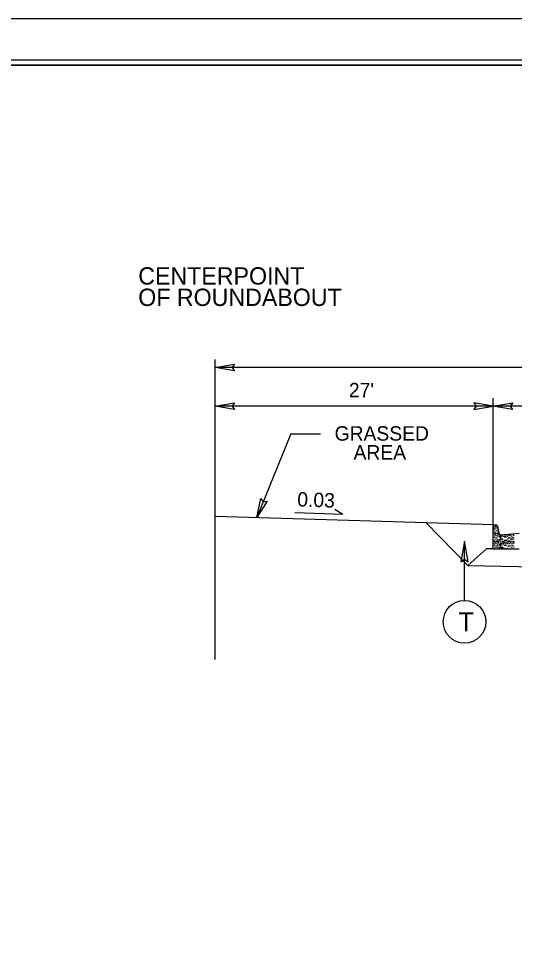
# Model space of a CAD drawing. Extents: x 1640342 to 1730599, y 538663 to 843747.
# Drawn here: x 1729959.6 to 1730007.7, y 538790.9 to 538882.2 of the extents above; entities that cross this region are included whole.
import ezdxf

# ---------------------------------------------------------------- set-up
doc = ezdxf.new("R2010")
doc.units = 0
for name, color, linetype in [('Default', 7, 'Continuous'), ('Prop Terminator CELL', 7, 'Continuous'), ('Sheet Plan CELL', 7, 'Continuous'), ('Sheet Plot Border Inside CELL', 7, 'Continuous'), ('Sheet Plot Border Outside CELL', 7, 'Continuous'), ('Typical Curb CELL', 7, 'Continuous'), ('Typical ID Circle CELL', 7, 'Continuous'), ('Typical Pavement Slope CELL', 7, 'Continuous'), ('Typical Pavement Slope Information CELL', 7, 'Continuous'), ('Typical Slope Point Local CELL', 7, 'Continuous'), ('Typical Terminator CELL', 7, 'Continuous'), ('Typical Text ID Circle CELL', 7, 'Continuous')]:
    doc.layers.add(name, color=color, linetype=linetype)

msp = doc.modelspace()

# ---------------------------------------------------------------- linework, layer by layer
at = {"layer": 'Default'}
for p, q in [((1729978.649, 538820.095), (1729978.649, 538849.183)), ((1730043.643, 538848.404), (1729978.649, 538848.404)), ((1730005.643, 538833.124), (1730005.643, 538845.435)), ((1730005.643, 538844.656), (1729978.649, 538844.656)), ((1730025.643, 538844.656), (1730005.643, 538844.656)), ((1729986.009, 538841.96), (1729982.691, 538833.852)), ((1729986.009, 538841.96), (1729988.889, 538841.96))]:
    msp.add_line(p, q, dxfattribs=at)
for points in [[(1729980.523, 538848.081), (1729978.649, 538848.404), (1729980.533, 538848.737), (1729980.294, 538848.404)], [(1729980.523, 538844.333), (1729978.649, 538844.656), (1729980.533, 538844.989), (1729980.294, 538844.656)], [(1730003.769, 538844.333), (1730005.643, 538844.656), (1730003.758, 538844.989), (1730003.998, 538844.656)], [(1730007.517, 538844.333), (1730005.643, 538844.656), (1730007.527, 538844.989), (1730007.288, 538844.656)]]:
    msp.add_lwpolyline(points, close=True, dxfattribs=at)
at = {"layer": 'Prop Terminator CELL'}
msp.add_lwpolyline([(1729983.694, 538835.455), (1729982.691, 538833.852), (1729983.094, 538835.712), (1729983.31, 538835.366)], close=True, dxfattribs=at)
at = {"layer": 'Sheet Plan CELL'}
for points in [[(1729873.99, 538667.718), (1729873.985, 538877.713), (1730133.983, 538877.721), (1730133.985, 538847.708), (1730173.993, 538847.706), (1730173.993, 538667.718)], [(1730173.998, 538877.718), (1729873.99, 538877.718), (1729873.99, 538667.718), (1730173.993, 538667.718)]]:
    msp.add_lwpolyline(points, close=True, dxfattribs=at)
at = {"layer": 'Sheet Plot Border Inside CELL'}
msp.add_lwpolyline([(1729843.293, 538667.216), (1730176.49, 538667.218), (1730176.493, 538878.216), (1729843.293, 538878.216)], close=True, dxfattribs=at)
at = {"layer": 'Sheet Plot Border Outside CELL'}
msp.add_lwpolyline([(1729840.693, 538663.216), (1730177.393, 538663.216), (1730177.393, 538882.216), (1729840.693, 538882.216)], close=True, dxfattribs=at)
at = {"layer": 'Typical Curb CELL'}
for p, q in [((1730005.848, 538833.039), (1730005.81, 538832.998)), ((1730005.81, 538832.998), (1730005.835, 538832.931)), ((1730005.835, 538832.931), (1730005.848, 538833.039)), ((1730005.711, 538832.721), (1730005.674, 538832.68)), ((1730005.674, 538832.68), (1730005.687, 538832.643)), ((1730005.711, 538832.402), (1730005.674, 538832.361)), ((1730005.674, 538832.361), (1730005.687, 538832.324)), ((1730005.701, 538832.644), (1730005.711, 538832.721)), ((1730005.701, 538832.324), (1730005.711, 538832.402)), ((1730005.848, 538832.271), (1730005.81, 538832.23)), ((1730005.81, 538832.23), (1730005.835, 538832.163)), ((1730005.835, 538832.163), (1730005.848, 538832.271)), ((1730006.083, 538832.308), (1730006.117, 538832.356)), ((1730006.1, 538832.233), (1730006.083, 538832.308)), ((1730006.117, 538832.356), (1730006.1, 538832.233)), ((1730006.224, 538832.095), (1730006.254, 538832.083)), ((1730006.239, 538831.993), (1730006.224, 538832.095)), ((1730006.254, 538832.083), (1730006.239, 538831.993)), ((1730006.371, 538832.13), (1730006.333, 538832.089)), ((1730006.333, 538832.089), (1730006.357, 538832.022)), ((1730006.357, 538832.022), (1730006.371, 538832.13)), ((1730006.621, 538832.117), (1730006.604, 538832.191)), ((1730006.745, 538831.978), (1730006.775, 538831.967)), ((1730006.753, 538831.919), (1730006.745, 538831.978)), ((1730006.891, 538832.013), (1730006.854, 538831.972)), ((1730006.881, 538831.925), (1730006.891, 538832.013)), ((1730006.967, 538832.211), (1730006.992, 538832.144)), ((1730007.356, 538832.247), (1730007.318, 538832.206)), ((1730007.318, 538832.206), (1730007.343, 538832.139)), ((1730007.343, 538832.139), (1730007.356, 538832.247)), ((1730007.608, 538832.209), (1730007.591, 538832.284)), ((1730005.711, 538831.953), (1730005.674, 538831.912)), ((1730005.674, 538831.912), (1730005.687, 538831.875)), ((1730005.711, 538831.634), (1730005.674, 538831.593)), ((1730005.674, 538831.593), (1730005.687, 538831.556)), ((1730005.711, 538831.147), (1730005.674, 538831.106)), ((1730005.674, 538831.106), (1730005.687, 538831.069)), ((1730005.701, 538831.875), (1730005.711, 538831.953)), ((1730005.701, 538831.556), (1730005.711, 538831.634)), ((1730005.701, 538831.069), (1730005.711, 538831.147)), ((1730005.848, 538831.465), (1730005.81, 538831.424)), ((1730005.81, 538831.424), (1730005.835, 538831.357)), ((1730005.835, 538831.357), (1730005.848, 538831.465)), ((1730006.083, 538831.502), (1730006.117, 538831.55)), ((1730006.1, 538831.427), (1730006.083, 538831.502)), ((1730006.117, 538831.55), (1730006.1, 538831.427)), ((1730006.224, 538831.775), (1730006.254, 538831.764)), ((1730006.239, 538831.674), (1730006.224, 538831.775)), ((1730006.224, 538831.288), (1730006.254, 538831.277)), ((1730006.239, 538831.187), (1730006.224, 538831.288)), ((1730006.254, 538831.764), (1730006.239, 538831.674)), ((1730006.254, 538831.277), (1730006.239, 538831.187)), ((1730006.324, 538831.901), (1730006.326, 538831.901)), ((1730006.324, 538831.582), (1730006.326, 538831.582)), ((1730006.324, 538831.095), (1730006.326, 538831.095)), ((1730006.371, 538831.811), (1730006.333, 538831.77)), ((1730006.333, 538831.77), (1730006.357, 538831.702)), ((1730006.371, 538831.324), (1730006.333, 538831.283)), ((1730006.333, 538831.283), (1730006.357, 538831.215)), ((1730006.357, 538831.702), (1730006.371, 538831.811)), ((1730006.357, 538831.215), (1730006.371, 538831.324)), ((1730006.367, 538831.903), (1730006.371, 538831.903)), ((1730006.367, 538831.584), (1730006.371, 538831.584)), ((1730006.367, 538831.097), (1730006.371, 538831.097)), ((1730006.55, 538831.911), (1730006.554, 538831.911)), ((1730006.55, 538831.591), (1730006.554, 538831.592)), ((1730006.55, 538831.105), (1730006.554, 538831.105)), ((1730006.604, 538831.385), (1730006.638, 538831.433)), ((1730006.621, 538831.31), (1730006.604, 538831.385)), ((1730006.638, 538831.433), (1730006.621, 538831.31)), ((1730006.745, 538831.659), (1730006.775, 538831.647)), ((1730006.753, 538831.6), (1730006.745, 538831.659)), ((1730006.745, 538831.172), (1730006.775, 538831.16)), ((1730006.753, 538831.113), (1730006.745, 538831.172)), ((1730006.775, 538831.967), (1730006.767, 538831.92)), ((1730006.775, 538831.647), (1730006.767, 538831.601)), ((1730006.775, 538831.16), (1730006.767, 538831.114)), ((1730006.854, 538831.972), (1730006.871, 538831.924)), ((1730006.891, 538831.694), (1730006.854, 538831.653)), ((1730006.854, 538831.653), (1730006.871, 538831.605)), ((1730006.891, 538831.207), (1730006.854, 538831.166)), ((1730006.854, 538831.166), (1730006.871, 538831.118)), ((1730006.881, 538831.605), (1730006.891, 538831.694)), ((1730006.881, 538831.118), (1730006.891, 538831.207)), ((1730006.967, 538831.405), (1730006.992, 538831.338)), ((1730007.219, 538831.93), (1730007.182, 538831.889)), ((1730007.182, 538831.889), (1730007.195, 538831.851)), ((1730007.219, 538831.61), (1730007.182, 538831.569)), ((1730007.182, 538831.569), (1730007.195, 538831.532)), ((1730007.219, 538831.147), (1730007.182, 538831.106)), ((1730007.182, 538831.106), (1730007.195, 538831.069)), ((1730007.209, 538831.852), (1730007.219, 538831.93)), ((1730007.209, 538831.533), (1730007.219, 538831.61)), ((1730007.209, 538831.069), (1730007.219, 538831.147)), ((1730007.356, 538831.465), (1730007.318, 538831.424)), ((1730007.318, 538831.424), (1730007.343, 538831.357)), ((1730007.343, 538831.357), (1730007.356, 538831.465)), ((1730007.591, 538831.502), (1730007.625, 538831.55)), ((1730007.608, 538831.427), (1730007.591, 538831.502)), ((1730007.625, 538831.55), (1730007.608, 538831.427)), ((1730003.16, 538829.222), (1730004.992, 538830.83)), ((1730005.649, 538830.83), (1730004.992, 538830.83)), ((1730006.224, 538830.969), (1730006.254, 538830.958)), ((1730006.239, 538830.868), (1730006.224, 538830.969)), ((1730006.254, 538830.958), (1730006.239, 538830.868)), ((1730006.371, 538831.004), (1730006.333, 538830.963)), ((1730006.333, 538830.963), (1730006.357, 538830.896)), ((1730006.357, 538830.896), (1730006.371, 538831.004)), ((1730006.745, 538830.853), (1730006.775, 538830.841)), ((1730006.753, 538830.794), (1730006.745, 538830.853)), ((1730006.775, 538830.841), (1730006.767, 538830.794)), ((1730006.891, 538830.888), (1730006.854, 538830.847))]:
    msp.add_line(p, q, dxfattribs=at)
for centre in [(1730005.643, 538833.035), (1730005.653, 538833.118), (1730005.677, 538832.957), (1730005.703, 538833.095), (1730005.728, 538832.935), (1730005.905, 538833.053), (1730005.908, 538832.883), (1730005.911, 538833.078), (1730005.958, 538833.014), (1730005.964, 538832.902), (1730005.967, 538833.096), (1730006.083, 538832.941), (1730005.643, 538832.267), (1730005.653, 538832.349), (1730005.668, 538832.875), (1730005.668, 538832.556), (1730005.668, 538832.107), (1730005.677, 538832.189), (1730005.703, 538832.327), (1730005.728, 538832.167), (1730005.745, 538832.781), (1730005.745, 538832.462), (1730005.745, 538832.013), (1730005.758, 538832.669), (1730005.758, 538832.35), (1730005.828, 538832.664), (1730005.828, 538832.344), (1730005.837, 538832.746), (1730005.837, 538832.427), (1730005.837, 538831.978), (1730005.853, 538832.855), (1730005.853, 538832.536), (1730005.853, 538832.087), (1730005.901, 538832.859), (1730005.901, 538832.54), (1730005.901, 538832.091), (1730005.905, 538832.285), (1730005.908, 538832.564), (1730005.908, 538832.115), (1730005.911, 538832.309), (1730005.947, 538832.668), (1730005.947, 538832.349), (1730005.955, 538832.82), (1730005.955, 538832.5), (1730005.955, 538832.052), (1730005.958, 538832.246), (1730005.964, 538832.583), (1730005.964, 538832.134), (1730005.967, 538832.328), (1730006.003, 538832.687), (1730006.003, 538832.367), (1730006.015, 538832.88), (1730006.015, 538832.56), (1730006.015, 538832.112), (1730006.054, 538832.664), (1730006.054, 538832.345), (1730006.063, 538832.731), (1730006.063, 538832.412), (1730006.072, 538832.813), (1730006.072, 538832.494), (1730006.072, 538832.045), (1730006.083, 538832.173), (1730006.139, 538832.569), (1730006.139, 538832.12), (1730006.145, 538832.199), (1730006.151, 538832.427), (1730006.151, 538831.978), (1730006.164, 538832.308), (1730006.201, 538832.188), (1730006.211, 538832.012), (1730006.226, 538832.319), (1730006.284, 538832.154), (1730006.29, 538832.089), (1730006.322, 538831.973), (1730006.417, 538832.077), (1730006.423, 538831.976), (1730006.467, 538832.151), (1730006.489, 538832.033), (1730006.496, 538832.058), (1730006.518, 538832.129), (1730006.542, 538831.994), (1730006.552, 538832.076), (1730006.604, 538832.056), (1730006.66, 538832.004), (1730006.666, 538832.083), (1730006.685, 538832.191), (1730006.722, 538832.071), (1730006.746, 538832.202), (1730006.795, 538832.206), (1730006.804, 538832.038), (1730006.811, 538831.972), (1730006.848, 538832.167), (1730006.925, 538832.073), (1730006.993, 538831.999), (1730007.012, 538832.107), (1730007.05, 538831.988), (1730007.074, 538832.119), (1730007.123, 538832.122), (1730007.129, 538832.147), (1730007.151, 538832.243), (1730007.176, 538832.083), (1730007.185, 538832.165), (1730007.236, 538832.143), (1730007.253, 538831.989), (1730007.361, 538832.064), (1730007.409, 538832.067), (1730007.413, 538832.262), (1730007.416, 538832.092), (1730007.463, 538832.028), (1730007.466, 538832.222), (1730007.472, 538832.11), (1730007.523, 538832.088), (1730007.58, 538832.021), (1730007.591, 538832.149), (1730007.647, 538832.097), (1730007.653, 538832.175), (1730007.672, 538832.284), (1730005.643, 538831.461), (1730005.653, 538831.543), (1730005.668, 538831.787), (1730005.668, 538831.3), (1730005.677, 538831.383), (1730005.703, 538831.521), (1730005.728, 538831.36), (1730005.745, 538831.694), (1730005.745, 538831.207), (1730005.758, 538831.901), (1730005.758, 538831.582), (1730005.758, 538831.095), (1730005.828, 538831.896), (1730005.828, 538831.576), (1730005.828, 538831.089), (1730005.837, 538831.659), (1730005.837, 538831.172), (1730005.853, 538831.768), (1730005.853, 538831.281), (1730005.901, 538831.772), (1730005.901, 538831.285), (1730005.905, 538831.479), (1730005.908, 538831.796), (1730005.908, 538831.309), (1730005.911, 538831.503), (1730005.947, 538831.9), (1730005.947, 538831.58), (1730005.947, 538831.093), (1730005.955, 538831.732), (1730005.955, 538831.245), (1730005.958, 538831.44), (1730005.964, 538831.815), (1730005.964, 538831.328), (1730005.967, 538831.522), (1730006.003, 538831.918), (1730006.003, 538831.599), (1730006.003, 538831.112), (1730006.015, 538831.792), (1730006.015, 538831.305), (1730006.054, 538831.896), (1730006.054, 538831.577), (1730006.054, 538831.09), (1730006.063, 538831.963), (1730006.063, 538831.643), (1730006.063, 538831.157), (1730006.072, 538831.726), (1730006.072, 538831.239), (1730006.083, 538831.367), (1730006.139, 538831.801), (1730006.139, 538831.314), (1730006.145, 538831.393), (1730006.151, 538831.659), (1730006.151, 538831.172), (1730006.164, 538831.501), (1730006.201, 538831.382), (1730006.211, 538831.693), (1730006.211, 538831.206), (1730006.226, 538831.513), (1730006.274, 538831.516), (1730006.281, 538831.541), (1730006.284, 538831.348), (1730006.29, 538831.961), (1730006.29, 538831.769), (1730006.29, 538831.642), (1730006.29, 538831.282), (1730006.29, 538831.155), (1730006.322, 538831.653), (1730006.322, 538831.166), (1730006.328, 538831.477), (1730006.337, 538831.559), (1730006.387, 538831.537), (1730006.404, 538831.383), (1730006.417, 538831.758), (1730006.417, 538831.271), (1730006.423, 538831.657), (1730006.423, 538831.17), (1730006.465, 538831.525), (1730006.467, 538831.345), (1730006.476, 538831.427), (1730006.489, 538831.714), (1730006.489, 538831.227), (1730006.496, 538831.738), (1730006.496, 538831.251), (1730006.513, 538831.529), (1730006.518, 538831.809), (1730006.518, 538831.322), (1730006.52, 538831.553), (1730006.528, 538831.405), (1730006.542, 538831.675), (1730006.542, 538831.188), (1730006.552, 538831.757), (1730006.552, 538831.27), (1730006.567, 538831.489), (1730006.576, 538831.572), (1730006.604, 538831.737), (1730006.604, 538831.25), (1730006.626, 538831.549), (1730006.66, 538831.685), (1730006.66, 538831.198), (1730006.666, 538831.763), (1730006.666, 538831.276), (1730006.685, 538831.385), (1730006.722, 538831.752), (1730006.722, 538831.265), (1730006.728, 538831.488), (1730006.737, 538831.57), (1730006.746, 538831.396), (1730006.795, 538831.4), (1730006.802, 538831.424), (1730006.804, 538831.718), (1730006.804, 538831.232), (1730006.811, 538831.653), (1730006.811, 538831.166), (1730006.848, 538831.36), (1730006.858, 538831.443), (1730006.864, 538831.535), (1730006.871, 538831.559), (1730006.908, 538831.42), (1730006.918, 538831.495), (1730006.925, 538831.754), (1730006.925, 538831.267), (1730006.927, 538831.578), (1730006.938, 538831.961), (1730006.938, 538831.642), (1730006.938, 538831.155), (1730006.988, 538831.92), (1730006.988, 538831.601), (1730006.988, 538831.138), (1730006.993, 538831.68), (1730006.993, 538831.216), (1730007.007, 538831.506), (1730007.012, 538831.788), (1730007.012, 538831.325), (1730007.05, 538831.668), (1730007.049, 538831.497), (1730007.05, 538831.205), (1730007.074, 538831.799), (1730007.074, 538831.336), (1730007.098, 538831.5), (1730007.105, 538831.525), (1730007.123, 538831.34), (1730007.129, 538831.364), (1730007.132, 538831.954), (1730007.132, 538831.635), (1730007.132, 538831.172), (1730007.138, 538831.888), (1730007.138, 538831.569), (1730007.138, 538831.106), (1730007.151, 538831.461), (1730007.161, 538831.543), (1730007.176, 538831.764), (1730007.176, 538831.3), (1730007.185, 538831.383), (1730007.211, 538831.521), (1730007.236, 538831.36), (1730007.253, 538831.67), (1730007.253, 538831.207), (1730007.266, 538831.877), (1730007.266, 538831.558), (1730007.266, 538831.095), (1730007.336, 538831.872), (1730007.336, 538831.553), (1730007.336, 538831.089), (1730007.345, 538831.954), (1730007.345, 538831.635), (1730007.345, 538831.172), (1730007.361, 538831.744), (1730007.361, 538831.281), (1730007.409, 538831.748), (1730007.409, 538831.285), (1730007.413, 538831.479), (1730007.416, 538831.772), (1730007.416, 538831.309), (1730007.419, 538831.503), (1730007.455, 538831.876), (1730007.455, 538831.557), (1730007.455, 538831.093), (1730007.463, 538831.709), (1730007.463, 538831.245), (1730007.466, 538831.44), (1730007.472, 538831.791), (1730007.472, 538831.328), (1730007.475, 538831.522), (1730007.511, 538831.895), (1730007.511, 538831.575), (1730007.511, 538831.112), (1730007.523, 538831.769), (1730007.523, 538831.305), (1730007.562, 538831.872), (1730007.562, 538831.553), (1730007.562, 538831.09), (1730007.571, 538831.939), (1730007.571, 538831.62), (1730007.571, 538831.157), (1730007.58, 538831.702), (1730007.58, 538831.239), (1730007.591, 538831.367), (1730007.647, 538831.778), (1730007.647, 538831.314), (1730007.653, 538831.393), (1730007.659, 538831.955), (1730007.659, 538831.635), (1730007.659, 538831.172), (1730007.672, 538831.501), (1730005.668, 538830.981), (1730005.745, 538830.888), (1730005.837, 538830.852), (1730005.853, 538830.962), (1730005.901, 538830.966), (1730005.908, 538830.99), (1730005.955, 538830.926), (1730005.964, 538831.008), (1730006.015, 538830.986), (1730006.063, 538830.837), (1730006.072, 538830.92), (1730006.139, 538830.995), (1730006.151, 538830.853), (1730006.211, 538830.887), (1730006.29, 538830.963), (1730006.29, 538830.836), (1730006.322, 538830.847), (1730006.417, 538830.952), (1730006.423, 538830.851), (1730006.489, 538830.908), (1730006.496, 538830.932), (1730006.518, 538831.003), (1730006.542, 538830.869), (1730006.552, 538830.951), (1730006.604, 538830.931), (1730006.66, 538830.878), (1730006.666, 538830.957), (1730006.722, 538830.946), (1730006.804, 538830.912), (1730006.811, 538830.847), (1730006.925, 538830.948), (1730006.938, 538830.835), (1730006.993, 538830.897), (1730007.012, 538831.006), (1730007.05, 538830.886), (1730007.074, 538831.017), (1730007.132, 538830.852), (1730007.176, 538830.981), (1730007.253, 538830.888), (1730007.345, 538830.852), (1730007.361, 538830.962), (1730007.409, 538830.966), (1730007.416, 538830.99), (1730007.463, 538830.926), (1730007.472, 538831.008), (1730007.523, 538830.986), (1730007.571, 538830.837), (1730007.58, 538830.92), (1730007.647, 538830.995), (1730007.659, 538830.853)]:
    msp.add_ellipse(centre, major_axis=(0, -0.00526), ratio=0.5, dxfattribs=at)
for centre, start_param, end_param in [((1730006.325, 538831.906), 0.310577, 6.014239), ((1730006.325, 538831.587), 0.310577, 6.014239), ((1730006.325, 538831.1), 0.310577, 6.014239), ((1730006.369, 538831.906), 0.93197, 5.392847), ((1730006.369, 538831.587), 0.93197, 5.392847), ((1730006.369, 538831.1), 0.93197, 5.392847), ((1730006.552, 538831.908), 2.20153, 4.123287), ((1730006.552, 538831.589), 2.20153, 4.123287), ((1730006.552, 538831.102), 2.20153, 4.123287)]:
    msp.add_ellipse(centre, major_axis=(0, -0.00526), ratio=0.5, start_param=start_param, end_param=end_param, dxfattribs=at)
at = {"layer": 'Typical ID Circle CELL'}
msp.add_line((1730002.858, 538825.821), (1730002.858, 538831.574), dxfattribs=at)
msp.add_circle((1730002.858, 538823.751), 2.071, dxfattribs=at)
at = {"layer": 'Typical Pavement Slope CELL'}
for p, q in [((1730003.16, 538829.222), (1729999.086, 538833.391)), ((1730005.643, 538830.83), (1730005.643, 538833.164)), ((1730005.643, 538833.164), (1730005.893, 538833.164)), ((1730006.403, 538832.185), (1730008.143, 538832.33)), ((1730005.643, 538830.83), (1730008.143, 538830.83)), ((1730003.16, 538829.222), (1730049.023, 538828.187))]:
    msp.add_line(p, q, dxfattribs=at)
for centre, start_param, end_param in [((1730005.893, 538832.664), 4.73364, 6.283185), ((1730006.393, 538832.685), 1.592047, 3.183219)]:
    msp.add_ellipse(centre, major_axis=(0, 0.5), ratio=0.5, start_param=start_param, end_param=end_param, dxfattribs=at)
at = {"layer": 'Typical Pavement Slope Information CELL'}
for q in [(1729986.381, 538834.322), (1729990.262, 538834.645)]:
    msp.add_line((1729991.038, 538834.16), q, dxfattribs=at)
at = {"layer": 'Typical Slope Point Local CELL'}
msp.add_line((1730005.643, 538833.164), (1729978.649, 538833.973), dxfattribs=at)
at = {"layer": 'Typical Terminator CELL'}
msp.add_lwpolyline([(1730003.204, 538829.566), (1730002.858, 538831.574), (1730002.501, 538829.555), (1730002.858, 538829.812)], close=True, dxfattribs=at)

# ---------------------------------------------------------------- texts
at = {"layer": 'Default'}
for s, p in [('CENTERPOINT', (1729971.182, 538856.445)), ('OF ROUNDABOUT', (1729971.182, 538854.373))]:
    msp.add_text(s, height=1.68295, dxfattribs=at).set_placement(p)
for s, p in [("27'", (1729991.63, 538845.512)), ('GRASSED', (1729990.243, 538841.312)), ('AREA', (1729992.084, 538839.477))]:
    msp.add_text(s, height=1.4, rotation=360, dxfattribs=at).set_placement(p)
at = {"layer": 'Typical Pavement Slope Information CELL'}
msp.add_text('0.03', height=1.4, rotation=358.01589, dxfattribs=at).set_placement((1729986.6, 538834.937))
at = {"layer": 'Typical Text ID Circle CELL'}
msp.add_text('T', height=1.854, dxfattribs=at).set_placement((1730002.265, 538822.824))

doc.saveas('drawing.dxf')
